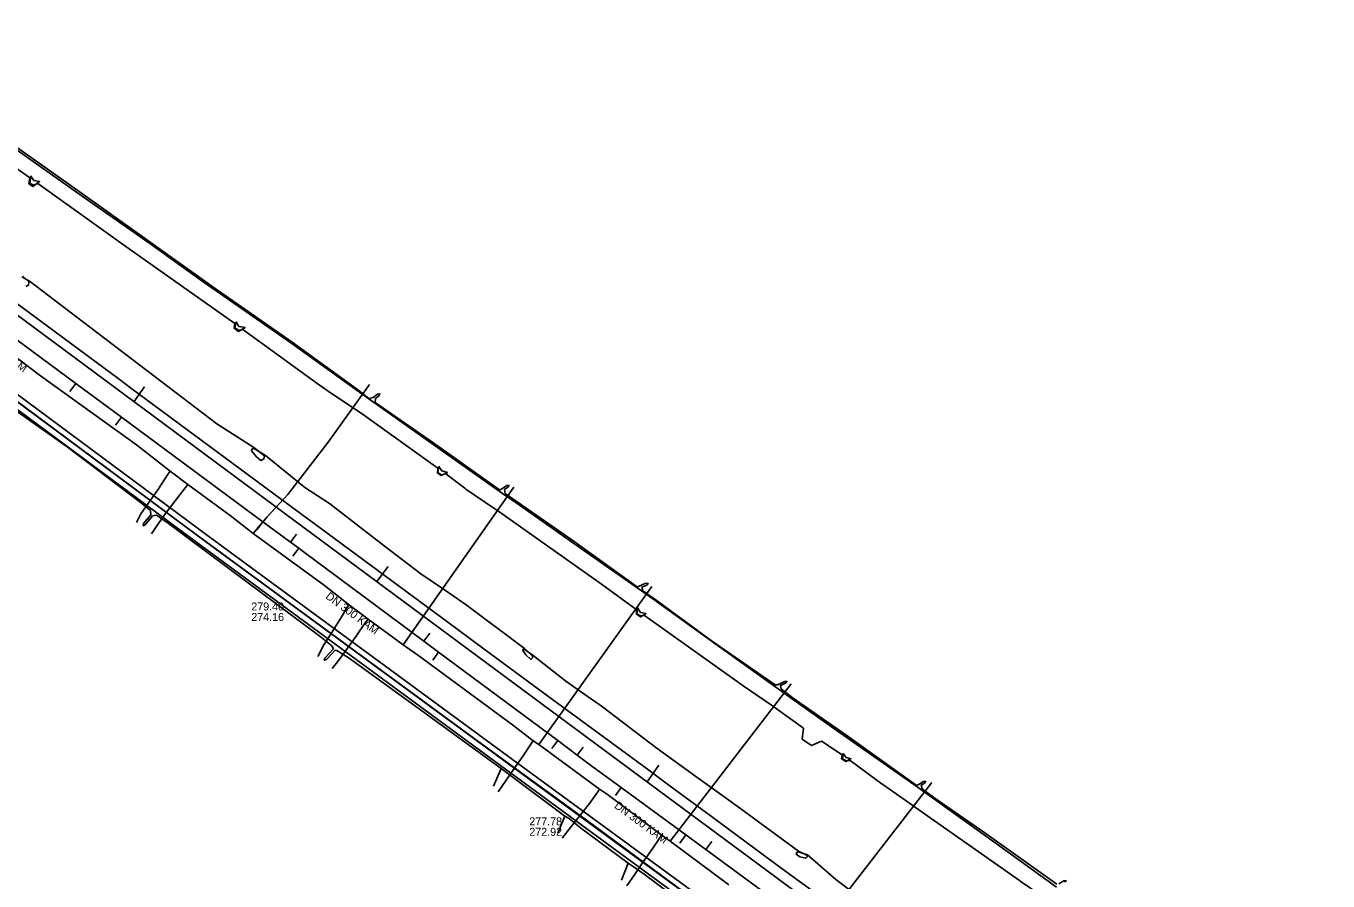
# Model space of a CAD drawing. Extents: x -598233 to -596890, y -1157848 to -1156431.
# Drawn here: x -597596.8 to -597466.7, y -1156803.5 to -1156718 of the extents above; entities that cross this region are included whole.
import ezdxf

# ---------------------------------------------------------------- set-up
doc = ezdxf.new("R2010")
doc.units = 0
for name, color, linetype in [('Vrstva 1', 7, 'Continuous'), ('Vrstva 13', 7, 'Continuous'), ('Vrstva 19', 7, 'Continuous'), ('Vrstva 25', 7, 'Continuous'), ('Vrstva 26', 7, 'Continuous'), ('Vrstva 42', 7, 'Continuous'), ('Vrstva 44', 7, 'Continuous'), ('Vrstva 5', 7, 'Continuous'), ('Vrstva 55', 7, 'Continuous'), ('Vrstva 8', 7, 'Continuous')]:
    doc.layers.add(name, color=color, linetype=linetype)

msp = doc.modelspace()

# ---------------------------------------------------------------- linework, layer by layer
at = {"layer": 'Vrstva 1'}
for points in [[(-597606.99, -1156740.07), (-597570.99, -1156766.77)], [(-597586.06, -1156755.59), (-597585, -1156754.11)], [(-597570.99, -1156766.77), (-597537.15, -1156791.82)], [(-597561.79, -1156773.58), (-597560.66, -1156772.07)], [(-597537.15, -1156791.82), (-597503.03, -1156817.1), (-597504.95, -1156827.2)], [(-597534.77, -1156793.59), (-597533.61, -1156791.95)]]:
    msp.add_lwpolyline(points, dxfattribs=at)
at = {"layer": 'Vrstva 13'}
msp.add_lwpolyline([(-597599.6, -1156744.43), (-597589.07, -1156752.22), (-597587.68, -1156753.25), (-597586.26, -1156754.3), (-597571.44, -1156765.26), (-597570.43, -1156765.99), (-597569.15, -1156766.96), (-597568.68, -1156767.3), (-597554.69, -1156777.65), (-597553.66, -1156778.41), (-597551.32, -1156780.13), (-597544.58, -1156785.09), (-597539.49, -1156788.85), (-597534.73, -1156792.35), (-597532.59, -1156793.93), (-597528.33, -1156797.08), (-597521.27, -1156802.29), (-597517.51, -1156805.05)], dxfattribs=at)
at = {"layer": 'Vrstva 19'}
for points in [[(-597598.84, -1156750.42), (-597595.39, -1156753.01), (-597585.82, -1156759.92), (-597582.43, -1156762.54), (-597580.67, -1156763.86), (-597576.45, -1156766.97), (-597574.15, -1156768.78), (-597567.02, -1156773.97), (-597564.53, -1156775.95), (-597562.65, -1156777.34), (-597559.14, -1156779.92), (-597557.57, -1156781.01), (-597548.09, -1156788), (-597546.14, -1156789.5), (-597545.59, -1156789.88), (-597539.51, -1156794.32), (-597538.72, -1156794.86), (-597533.26, -1156798.96), (-597532.47, -1156799.55)], [(-597574.15, -1156768.78), (-597572.74, -1156767.09), (-597570.68, -1156764.87), (-597566.65, -1156759.63), (-597562.51, -1156753.88)], [(-597582.43, -1156762.54), (-597582.65, -1156762.81), (-597583.66, -1156764.39), (-597585.37, -1156766.79), (-597585.82, -1156767.67)], [(-597580.67, -1156763.86), (-597580.92, -1156764.16), (-597581.95, -1156765.49), (-597582.79, -1156766.65), (-597583.71, -1156767.92), (-597584.3, -1156768.81)], [(-597559.14, -1156779.92), (-597548.08, -1156764.15)], [(-597545.59, -1156789.88), (-597534.28, -1156774.06)], [(-597564.53, -1156775.95), (-597564.78, -1156776.25), (-597565.51, -1156777.44), (-597566.35, -1156778.77), (-597567.07, -1156779.92), (-597567.69, -1156781.07)], [(-597562.65, -1156777.34), (-597562.88, -1156777.6), (-597563.84, -1156779.05), (-597565.58, -1156781.45), (-597566.25, -1156782.26)], [(-597532.47, -1156799.55), (-597520.36, -1156783.82)], [(-597546.14, -1156789.5), (-597546.31, -1156789.75), (-597547.16, -1156791.01), (-597548.05, -1156792.26), (-597548.86, -1156793.42), (-597549.64, -1156794.59)], [(-597539.51, -1156794.32), (-597539.69, -1156794.6), (-597540.53, -1156795.76), (-597542.31, -1156798.05), (-597543.25, -1156799.25)], [(-597518.77, -1156809.78), (-597506.32, -1156793.68)], [(-597533.26, -1156798.96), (-597533.48, -1156799.21), (-597534.25, -1156800.32), (-597535.21, -1156801.71), (-597535.97, -1156802.81), (-597536.8, -1156803.99)], [(-597532.47, -1156799.55), (-597526.61, -1156803.91)]]:
    msp.add_lwpolyline(points, dxfattribs=at)
at = {"layer": 'Vrstva 25'}
msp.add_lwpolyline([(-597492.94, -1156832.97), (-597503.43, -1156825.14), (-597515.31, -1156816.32), (-597531.3, -1156804.51), (-597548.58, -1156791.84), (-597578.92, -1156769.56), (-597598.07, -1156755.35), (-597616.4, -1156741.77), (-597633.98, -1156728.85)], dxfattribs=at)
at = {"layer": 'Vrstva 26'}
for points in [[(-597493.69, -1156833.15), (-597503.78, -1156825.62), (-597515.67, -1156816.8), (-597531.65, -1156805), (-597548.93, -1156792.32), (-597579.28, -1156770.04), (-597598.43, -1156755.83), (-597616.75, -1156742.25), (-597634.34, -1156729.34)], [(-597633.23, -1156728.66), (-597616.04, -1156741.28), (-597597.71, -1156754.87), (-597578.56, -1156769.08), (-597548.22, -1156791.36), (-597530.94, -1156804.03), (-597514.95, -1156815.83), (-597503.07, -1156824.65), (-597492.58, -1156832.49)]]:
    msp.add_lwpolyline(points, dxfattribs=at)
at = {"layer": 'Vrstva 42'}
for points in [[(-597603.44, -1156726.19), (-597591.78, -1156734.41), (-597585.27, -1156739.05), (-597577.94, -1156744.26), (-597570.26, -1156749.64), (-597563.7, -1156754.38), (-597562.57, -1156755.26), (-597562.15, -1156755.18), (-597561.7, -1156754.85), (-597561.48, -1156754.81), (-597561.58, -1156755.01), (-597561.93, -1156755.26), (-597561.96, -1156755.67), (-597556.08, -1156759.73), (-597549.52, -1156764.41), (-597549.38, -1156764.37), (-597548.79, -1156763.98), (-597548.57, -1156763.95), (-597548.68, -1156764.14), (-597549.03, -1156764.38), (-597548.97, -1156764.76), (-597547.76, -1156765.59), (-597542.3, -1156769.41), (-597535.77, -1156774.12), (-597535.61, -1156774.08), (-597534.88, -1156773.75), (-597534.66, -1156773.76), (-597534.8, -1156773.93), (-597535.28, -1156774.15), (-597535.19, -1156774.5), (-597533.98, -1156775.35), (-597528.23, -1156779.56), (-597521.96, -1156783.92), (-597521.73, -1156783.9), (-597521.01, -1156783.56), (-597520.79, -1156783.56), (-597520.93, -1156783.74), (-597521.42, -1156783.97), (-597521.35, -1156784.3), (-597520.16, -1156785.23), (-597514.89, -1156788.89), (-597507.86, -1156793.93), (-597507.67, -1156793.89), (-597507.13, -1156793.56), (-597506.91, -1156793.54), (-597507.03, -1156793.73), (-597507.36, -1156793.93), (-597507.27, -1156794.31), (-597506.12, -1156795.16), (-597501.02, -1156798.71), (-597493.81, -1156803.83)], [(-597466.71, -1156857.63), (-597467.51, -1156855.36), (-597468.13, -1156853.85), (-597469.6, -1156850.91), (-597471.15, -1156848.42), (-597473.47, -1156845.3), (-597478.26, -1156840.49), (-597480.79, -1156838.62), (-597482.51, -1156837.5), (-597482.94, -1156837.15), (-597483.35, -1156837.12), (-597483.66, -1156837.34), (-597484.68, -1156838.86), (-597484.75, -1156838.91), (-597484.92, -1156838.91), (-597493.01, -1156832.89), (-597503.05, -1156825.39), (-597516.22, -1156815.61), (-597540.24, -1156797.88), (-597551.7, -1156789.52), (-597576.08, -1156771.63), (-597580.61, -1156768.3), (-597603.52, -1156751.29)], [(-597584.94, -1156767.9), (-597585.14, -1156767.99), (-597585.09, -1156767.77), (-597584.36, -1156766.89), (-597584.4, -1156766.48), (-597585.56, -1156765.54), (-597592.74, -1156760.11), (-597600.8, -1156754.43)], [(-597530.01, -1156806.65), (-597535.07, -1156802.85), (-597536.25, -1156802), (-597536.65, -1156801.73), (-597541.42, -1156798.19), (-597542.55, -1156797.26), (-597542.98, -1156797.05), (-597547.9, -1156793.37), (-597549.08, -1156792.48), (-597549.36, -1156792.27), (-597557.66, -1156786.25), (-597564.55, -1156781.24), (-597565.78, -1156780.46), (-597565.95, -1156780.43), (-597566.82, -1156781.37), (-597567.03, -1156781.45), (-597566.97, -1156781.24), (-597566.12, -1156780.31), (-597566.27, -1156780.01), (-597567.46, -1156779.08), (-597574.88, -1156773.53), (-597582.6, -1156767.78), (-597583.82, -1156766.93), (-597584.2, -1156767), (-597584.94, -1156767.9)], [(-597549.36, -1156792.27), (-597550.12, -1156794.03)], [(-597542.98, -1156797.05), (-597543.7, -1156798.72)], [(-597536.65, -1156801.73), (-597537.31, -1156803.43)], [(-597493.6, -1156803.81), (-597493.11, -1156803.49), (-597492.89, -1156803.46), (-597493, -1156803.65)]]:
    msp.add_lwpolyline(points, dxfattribs=at)
at = {"layer": 'Vrstva 44'}
msp.add_lwpolyline([(-597493.83, -1156804.15), (-597499.87, -1156799.78), (-597506.33, -1156795.13), (-597507.77, -1156794.11), (-597515.77, -1156788.5), (-597520.22, -1156785.34), (-597521.67, -1156784.32), (-597528, -1156779.78), (-597534.21, -1156775.32), (-597535.66, -1156774.28), (-597541.42, -1156770.25), (-597547.74, -1156765.78), (-597549.22, -1156764.78), (-597556.84, -1156759.37), (-597562.35, -1156755.48), (-597563.76, -1156754.48), (-597570.39, -1156749.71), (-597579.39, -1156743.45), (-597584.47, -1156739.78), (-597591.56, -1156734.81), (-597603.13, -1156726.64)], dxfattribs=at)
at = {"layer": 'Vrstva 5'}
for p, q in [((-597592.47, -1156754.58), (-597591.87, -1156753.77)), ((-597587.92, -1156757.94), (-597587.32, -1156757.14)), ((-597573.76, -1156768.41), (-597573.16, -1156767.6)), ((-597569.81, -1156768.84), (-597570.4, -1156769.64)), ((-597570.18, -1156771.05), (-597569.59, -1156770.24)), ((-597556.47, -1156778.74), (-597557.07, -1156779.54)), ((-597556.2, -1156781.43), (-597555.61, -1156780.63)), ((-597544.3, -1156790.28), (-597543.7, -1156789.48)), ((-597541.16, -1156790.12), (-597541.76, -1156790.92)), ((-597537.94, -1156794.98), (-597537.35, -1156794.17)), ((-597531.48, -1156799.72), (-597530.89, -1156798.91)), ((-597528.3, -1156799.57), (-597528.9, -1156800.37))]:
    msp.add_line(p, q, dxfattribs=at)
for points in [[(-597604.73, -1156744.27), (-597591.87, -1156753.77), (-597587.32, -1156757.14), (-597573.16, -1156767.6), (-597570.4, -1156769.64), (-597569.59, -1156770.24), (-597569.01, -1156770.67)], [(-597569.01, -1156770.67), (-597557.07, -1156779.54), (-597555.61, -1156780.63), (-597543.7, -1156789.48), (-597541.76, -1156790.92), (-597540.28, -1156792.02)], [(-597540.28, -1156792.02), (-597537.35, -1156794.17), (-597530.89, -1156798.91), (-597528.9, -1156800.37), (-597524.36, -1156803.7), (-597516.51, -1156809.46), (-597515.18, -1156810.43), (-597509.09, -1156814.9), (-597505.33, -1156817.66)]]:
    msp.add_lwpolyline(points, dxfattribs=at)
at = {"layer": 'Vrstva 55'}
for points in [[(-597617.34, -1156718.45), (-597617.61, -1156718.03), (-597617.73, -1156718.59), (-597617.34, -1156718.85), (-597616.93, -1156718.74), (-597608.88, -1156724.51), (-597601.81, -1156729.46), (-597596.61, -1156733.11), (-597596.48, -1156733.2), (-597596.55, -1156733.8), (-597596.15, -1156734.06), (-597595.49, -1156733.59), (-597596.07, -1156733.49)], [(-597596.07, -1156733.49), (-597596.36, -1156733.03), (-597596.48, -1156733.75), (-597596.13, -1156733.95), (-597595.66, -1156733.78), (-597586.64, -1156740.25), (-597575.97, -1156747.79), (-597576.03, -1156748.25), (-597575.6, -1156748.56), (-597574.95, -1156748.19), (-597575.56, -1156748.08)], [(-597597.27, -1156743.12), (-597596.51, -1156743.53), (-597595.96, -1156743.95), (-597577.78, -1156757.82), (-597574.06, -1156760.18), (-597573, -1156761.02), (-597573.07, -1156761.31), (-597573.36, -1156761.46), (-597573.8, -1156761.12), (-597574.32, -1156760.51), (-597574.25, -1156760.33), (-597574.12, -1156760.25), (-597572.92, -1156760.98), (-597568.97, -1156764.17), (-597566.52, -1156765.78), (-597561.05, -1156770.01), (-597557.39, -1156772.8), (-597555.03, -1156774.42), (-597552.86, -1156775.91), (-597547.02, -1156780.28), (-597546.21, -1156781.05), (-597546.23, -1156781.22), (-597546.39, -1156781.36), (-597546.9, -1156780.92), (-597547.19, -1156780.48), (-597547.15, -1156780.36), (-597547.07, -1156780.33), (-597546.17, -1156780.98), (-597545.07, -1156781.84), (-597542.88, -1156783.55), (-597541.31, -1156784.65), (-597539.23, -1156786.11), (-597533.88, -1156790.18), (-597529.9, -1156793.07), (-597527.81, -1156794.58), (-597525.41, -1156796.31), (-597519.63, -1156800.55), (-597518.79, -1156800.93), (-597518.78, -1156801.1), (-597518.91, -1156801.25), (-597519.5, -1156801.11), (-597519.85, -1156800.82), (-597519.8, -1156800.67), (-597519.67, -1156800.6), (-597518.73, -1156800.9), (-597517.45, -1156802.02), (-597515.9, -1156803.38), (-597514, -1156804.79)], [(-597597.17, -1156743.04), (-597596.55, -1156743.62), (-597596.59, -1156743.94), (-597596.87, -1156744.08)], [(-597575.56, -1156748.08), (-597575.85, -1156747.62), (-597575.97, -1156748.2), (-597575.61, -1156748.44), (-597575.16, -1156748.37), (-597567.64, -1156753.84), (-597566.63, -1156754.53), (-597563.73, -1156756.5), (-597563.36, -1156756.75), (-597555.7, -1156762.23), (-597555.73, -1156762.72), (-597555.36, -1156762.97), (-597554.72, -1156762.66), (-597555.29, -1156762.52)], [(-597555.29, -1156762.52), (-597555.58, -1156762.08), (-597555.67, -1156762.67), (-597555.34, -1156762.9), (-597554.89, -1156762.82), (-597553, -1156764.25), (-597552.89, -1156764.33), (-597549.97, -1156766.31), (-597549.59, -1156766.57), (-597539.55, -1156773.67), (-597538.97, -1156774.09), (-597536.12, -1156776.16), (-597535.83, -1156776.38), (-597535.83, -1156776.84), (-597535.43, -1156777.11), (-597534.86, -1156776.78), (-597535.42, -1156776.67)], [(-597535.42, -1156776.67), (-597535.71, -1156776.22), (-597535.79, -1156776.8), (-597535.44, -1156777.02), (-597535.01, -1156776.96), (-597525.53, -1156783.75), (-597525.15, -1156784.02), (-597522.24, -1156786.01), (-597521.73, -1156786.36), (-597519.13, -1156788.24), (-597519.28, -1156789.33), (-597518.34, -1156789.98), (-597517.32, -1156789.54), (-597515.28, -1156790.89), (-597515.32, -1156791.3), (-597514.9, -1156791.58), (-597514.4, -1156791.29), (-597514.86, -1156791.16)], [(-597514.86, -1156791.16), (-597515.17, -1156790.78), (-597515.24, -1156791.26), (-597514.89, -1156791.49), (-597514.46, -1156791.46), (-597511.27, -1156793.82), (-597511.2, -1156793.87), (-597508.32, -1156795.9), (-597507.95, -1156796.16), (-597497.54, -1156803.47), (-597497.37, -1156803.59), (-597494.49, -1156805.56), (-597493.31, -1156806.37), (-597493.31, -1156806.86), (-597492.91, -1156807.1), (-597492.38, -1156806.82), (-597492.9, -1156806.65)]]:
    msp.add_lwpolyline(points, dxfattribs=at)

# ---------------------------------------------------------------- texts
at = {"layer": 'Vrstva 8'}
for rotation, p in [(323.5326, (-597602.12, -1156748.98)), (323.383, (-597566.97, -1156775.2)), (323.7355, (-597538.11, -1156796.14))]:
    msp.add_text('DN 300 KAM', height=0.8, rotation=rotation, dxfattribs=at).set_placement(p)
for s, p in [('279.40', (-597574.33, -1156776.47)), ('274.16', (-597574.33, -1156777.52)), ('277.78', (-597546.54, -1156797.95)), ('272.92', (-597546.54, -1156799))]:
    msp.add_text(s, height=0.8, dxfattribs=at).set_placement(p)

doc.saveas('drawing.dxf')
